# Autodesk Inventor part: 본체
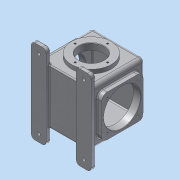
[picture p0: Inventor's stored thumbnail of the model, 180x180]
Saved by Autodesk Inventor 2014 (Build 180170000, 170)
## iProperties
Created: 2026-01
Part Number: 본체
Material: 알루미늄 6061
Document SubType Name: Modeling
Designer: dg
Density: 2.71 g/cm^3
Appearance: 알루미늄 - 평지
Mass: 2726.38 g
Surface Area: 2463.16 cm^2
Volume: 1006.05 cm^3
Author: dg
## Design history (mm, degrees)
sketch "스케치1"
  geometry: L1 (-74, 74)-(74, 74); L2 (74, 74)-(74, -74); L3 (74, -74)-(-74, -74); L4 (-74, -74)-(-74, 74); L5 (-74, 74)-(74, -74); L6 (74, 74)-(-74, -74); 1 further point
  constraints: 12 end point, 2 midpoint, 2 parallel, 1 horizontal, 1 perpendicular
  dimensions: "d0" = 148 distance of L1.end L2.end; "d1" = 148 distance between parallel lines of L4 L2
extrude "돌출1" new body sketch "스케치1" stored distance "d2" = 142; taper "d3" = 0 deg
fillet "모깎기1" dims "d4" = 10
fillet "모깎기2" dims "d5" = 10, "d72" = 3
feature "쉘1" dims "d6" = 7
sketch "스케치3"
  geometry: L1 (-56, -56)-(56, -56); L2 (56, -56)-(56, 56); L3 (56, 56)-(-56, 56); L4 (-56, 56)-(-56, -56); L5 (-56, -56)-(56, 56); L6 (56, -56)-(-56, 56); 1 further point
  constraints: 12 end point, 2 midpoint, 2 parallel, 1 horizontal, 1 perpendicular
  dimensions: "d10" = 112 distance of L3.end L2.end; "d11" = 112 distance of L2.end L1.end
extrude "돌출3" join sketch "스케치3" distance "d12" = 13; taper "d13" = 0 deg
sketch "스케치4"
  geometry: C1 r 50 at (0, 0); 1 further point
  constraints: 1 centre point, 1 coincident
  dimensions: "d14" = 100 diameter of C1
extrude "돌출4" cut sketch "스케치4" stored distance "d15" = 13; taper "d16" = 0 deg
sketch "스케치6"
  geometry: C1 r 50 at (0, 0) reference; 1 further point
  dimensions: "d31" = 41 horizontal distance of C1.centre point (-41, 41); "d32" = 41 horizontal distance of C1.centre point (-41, 41)
hole "구멍2" sketch "스케치6" at (-41, 41) diameter "d33" = 4.917; stored, may be unused: countersink angle "d37" = 90 deg, drill point angle "d39" = 118 deg; dims "d34" = 12, "d35" = 4, "d36" = 2, "d38" = 14
sketch "스케치7"
  geometry: L1 (81, -82)-(41, -82); L2 (41, -82)-(41, -70); L3 (41, -70)-(81, -70); L4 (81, -70)-(81, -82); L5 (-61, 74)-(61, 74) reference; 1 further point
  constraints: 8 end point, 2 parallel, 1 horizontal, 1 perpendicular
  dimensions: "d46" = 40 distance of L2.end L3.end; "d47" = 12 distance of L1.end L2.end; "d48" = 156 distance between parallel lines of L1 L5; "d49" = 81 distance from line of point (0, 0) L4
extrude "돌출6" join sketch "스케치7" stored distance "d50" = 228; taper "d51" = 0 deg
fillet "모깎기3" dims "d52" = 10
fillet "모깎기4" dims "d68" = 15
fillet "모깎기8" dims "d73" = 3
sketch "스케치9"
  geometry: 2 further points
  dimensions: "d74" = 94 vertical distance of point (20, -168) point (-41, -74); "d75" = 61 horizontal distance of point (20, -168) point (-41, -74)
hole "구멍4" sketch "스케치9" at (20, -168) diameter "d76" = 9; stored, may be unused: countersink angle "d80" = 90 deg, drill point angle "d82" = 118 deg; dims "d77" = 12, "d78" = 24, "d79" = 2, "d81" = 14
fillet "모깎기9" dims "d89" = 3
fillet "모깎기10" dims "d90" = 3
fillet "모깎기11" dims "d91" = 3
sketch "스케치10"
  geometry: 2 further points
  constraints: 1 coincident, 1 other
feature "엠보싱1" sketch "스케치10" dims "d0" = 148, "d1" = 148, "d10" = 112, "d92" = 0.5, "d93" = 0
sketch "스케치11"
  geometry: C1 r 54 at (61, -64); 1 further point
  constraints: 1 centre point, 1 coincident
  dimensions: "d94" = 108 diameter of C1
extrude "돌출7" join sketch "스케치11" distance "d95" = 11; taper "d96" = 0 deg
sketch "스케치12"
  geometry: C1 r 54 at (0, 0) reference; C2 r 34 at (0, 0); 1 further point
  constraints: 1 centre point, 1 coincident, 1 vertical alignment
  dimensions: "d97" = 68 diameter of C2; "d98" = 44 distance of C1.centre point (0, 44)
hole "구멍5" sketch "스케치12" diameter "d99" = 4.917; stored, may be unused: countersink angle "d103" = 90 deg, drill point angle "d105" = 118 deg; dims "d100" = 12, "d101" = 24, "d102" = 2, "d104" = 14
extrude "돌출8" cut sketch "스케치12" stored distance "d109" = 11; taper "d110" = 0 deg
chamfer "모따기1" distance "d111" = 1; stored, may be unused: second distance "d112" = 2, angle "d113" = 45 deg
node "솔리드1"
mirror "대칭1"
pattern_linear "직사각형 패턴1" dims "d42" = 82, "d45" = 82
mirror "대칭2"
mirror "대칭3"
pattern_linear "직사각형 패턴3" dims "d85" = 188, "d88" = 122
pattern_circular "원형 패턴2" dims angle "d107" = 360 deg
